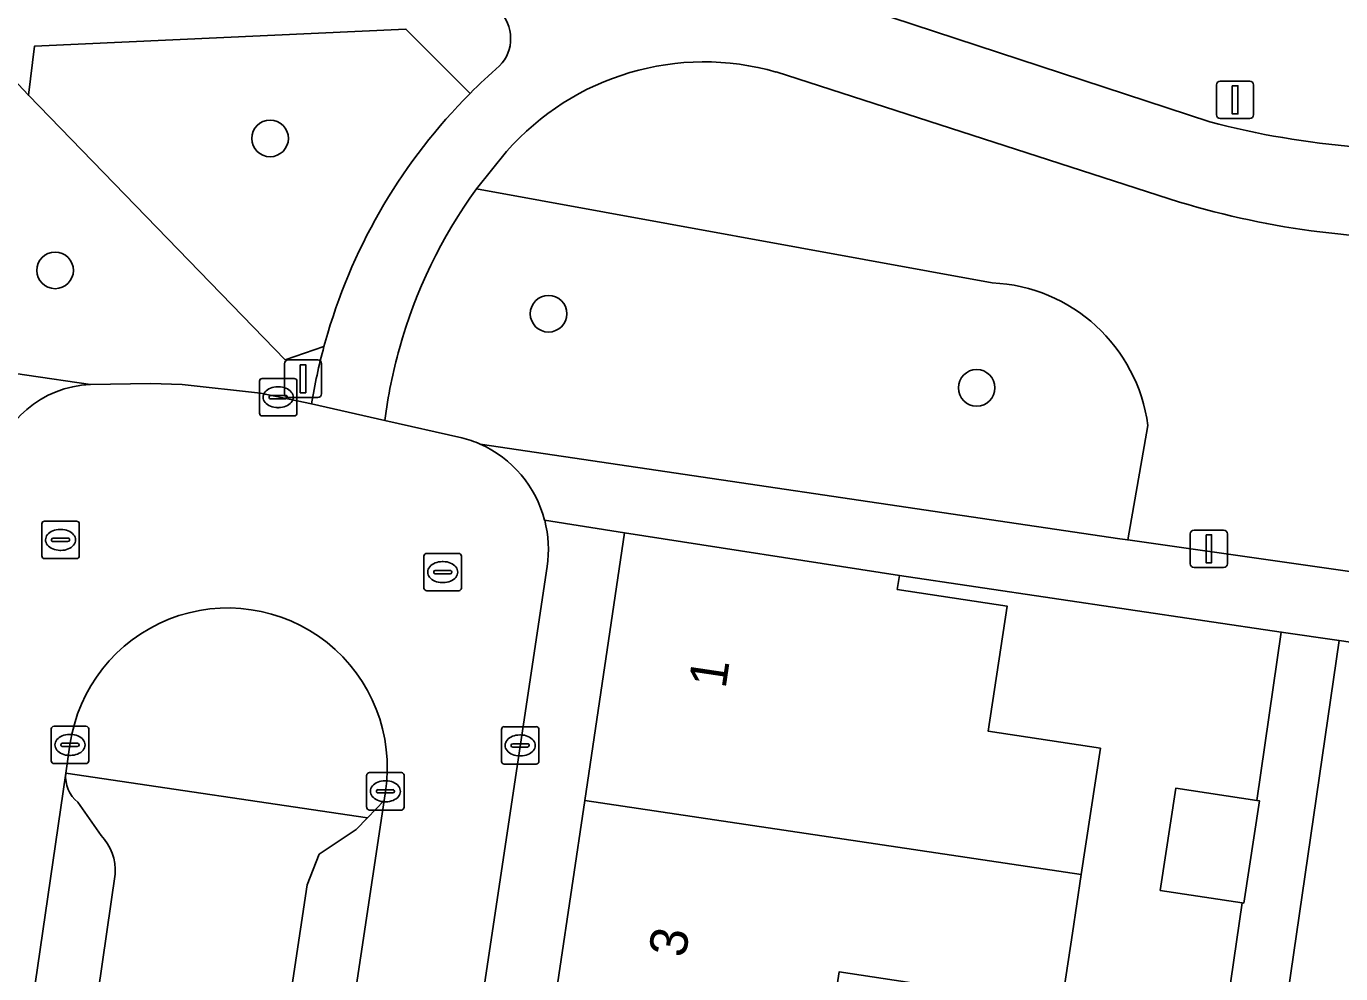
# Model space of a CAD drawing. Extents: x 163683 to 164494, y 382709 to 383872.
# Drawn here: x 164102.44 to 164137.55, y 383063.32 to 383088.61 of the extents above; entities that cross this region are included whole.
import ezdxf

# ---------------------------------------------------------------- set-up
doc = ezdxf.new("R2010")
doc.units = 0
for name, color, linetype in [('IMGEO_Boom', 7, 'Continuous'), ('IMGEO_Erf', 7, 'Continuous'), ('IMGEO_Groenvoorziening', 7, 'Continuous'), ('IMGEO_Kolk', 7, 'Continuous'), ('IMGEO_Lichtmast', 7, 'Continuous'), ('IMGEO_Pand', 7, 'Continuous'), ('IMGEO_Pand_nummerreeks', 7, 'Continuous'), ('IMGEO_Parkeervlak_open', 7, 'Continuous'), ('IMGEO_Rijbaan_lokaal_open', 7, 'Continuous'), ('IMGEO_Rioolput', 7, 'Continuous'), ('IMGEO_Voetpad_halfverhard', 7, 'Continuous'), ('IMGEO_Voetpad_onverhard', 7, 'Continuous'), ('IMGEO_Voetpad_open', 7, 'Continuous')]:
    doc.layers.add(name, color=color, linetype=linetype)

msp = doc.modelspace()

# ---------------------------------------------------------------- linework, layer by layer
at = {"layer": 'IMGEO_Boom'}
for centre in [(164108.954, 383085.621), (164103.212, 383082.097), (164116.392, 383080.939), (164127.828, 383078.96)]:
    msp.add_circle(centre, 0.489, dxfattribs=at)
at = {"layer": 'IMGEO_Erf'}
for points in [[(164134.915, 383065.209), (164132.733, 383065.541), (164133.149, 383068.274), (164135.312, 383067.944), (164135.965, 383072.44), (164125.764, 383073.946), (164125.708, 383073.578), (164128.64, 383073.132), (164128.133, 383069.794), (164131.135, 383069.339), (164130.623, 383065.966), (164130.384, 383064.396), (164130.091, 383062.468), (164124.158, 383063.368), (164123.625, 383059.857), (164123.087, 383056.319), (164129.021, 383055.419), (164128.733, 383053.521), (164128.499, 383051.98), (164127.982, 383048.577), (164122.049, 383049.477), (164121.476, 383045.707), (164131.862, 383044.198)], [(164146.251, 383060.095), (164140.317, 383060.973), (164140.602, 383062.903), (164140.829, 383064.44), (164141.333, 383067.849), (164147.268, 383066.971), (164147.817, 383070.691), (164137.509, 383072.212), (164133.407, 383043.974), (164143.649, 383042.486), (164144.194, 383046.176), (164138.26, 383047.054), (164138.767, 383050.485), (164136.597, 383050.805), (164136.989, 383053.462), (164139.16, 383053.142), (164139.279, 383053.95), (164145.213, 383053.072), (164145.733, 383056.587)]]:
    msp.add_lwpolyline(points, close=True, dxfattribs=at)
at = {"layer": 'IMGEO_Groenvoorziening'}
for points in [[(164063.914, 383096.136), (164060.271, 383092.698), (164059.314, 383087.6), (164060.473, 383085.465), (164077.551, 383082.956), (164078.62, 383087.621), (164097.665, 383084.707), (164099.049, 383079.797), (164104.156, 383079.047), (164105.76, 383079.073), (164106.604, 383079.047), (164108.694, 383078.814), (164110.063, 383078.532)], [(164110.394, 383080.065), (164109.361, 383079.71), (164102.501, 383086.771), (164098.441, 383091.102)], [(164122.556, 383089.943), (164123.88, 383089.409), (164134.057, 383086.059)], [(164114.296, 383086.819), (164112.582, 383088.541), (164102.66, 383088.082), (164102.501, 383086.771), (164109.361, 383079.71), (164110.394, 383080.065), (164110.494, 383080.419)], [(164133.248, 383083.922), (164122.474, 383087.394)], [(164115.27, 383085.27), (164114.466, 383084.27), (164128.244, 383081.764)], [(164128.244, 383081.764), (164114.466, 383084.27)], [(164112.022, 383078.091), (164114.08, 383077.628)], [(164114.568, 383077.457), (164131.649, 383074.93), (164131.864, 383074.9), (164132.4, 383077.957)], [(164132.4, 383077.957), (164131.864, 383074.9), (164157.283, 383071.277), (164153.793, 383047.768), (164153.917, 383047.788)], [(164103.609, 383069.43), (164103.498, 383068.668), (164111.555, 383067.478), (164111.998, 383067.938), (164112.035, 383068.184)], [(164104.819, 383065.979), (164102.872, 383052.545), (164107.85, 383051.778), (164109.948, 383065.689), (164110.267, 383066.508), (164111.254, 383067.165), (164111.555, 383067.478), (164103.498, 383068.668)], [(164103.822, 383067.893), (164104.439, 383067.008)]]:
    msp.add_lwpolyline(points, dxfattribs=at)
for centre, radius, start, end in [((164120.547, 383080.652), 7.012, 74.0446, 138.8102), ((164125.056, 383076.098), 15.19, 135.1027, 163.4713), ((164139.889, 383108.442), 23.13, 255.3969, 275.1179), ((164125.256, 383076.427), 13.339, 143.9868, 164.4007), ((164139.731, 383105.192), 22.236, 253.0504, 272.8188), ((164128.05, 383077.38), 4.388, 7.5513, 87.4677), ((164128.05, 383077.38), 4.388, 7.5513, 87.4677), ((164124.663, 383076.182), 14.788, 164.7763, 170.8556), ((164125.37, 383076.412), 13.453, 164.4696, 172.8303), ((164113.342, 383074.74), 2.981, 65.714, 75.6641), ((164107.825, 383068.824), 4.259, 351.3566, 171.82), ((164104.369, 383068.577), 0.875, 174.0139, 231.3623), ((164103.435, 383066.052), 1.386, 356.9611, 43.5764)]:
    msp.add_arc(centre, radius, start, end, dxfattribs=at)
at = {"layer": 'IMGEO_Kolk'}
for p, q in [((164108.67, 383078.285), (164108.67, 383079.137)), ((164108.745, 383079.211), (164109.597, 383079.211)), ((164109.671, 383079.137), (164109.671, 383078.285)), ((164108.972, 383078.754), (164109.37, 383078.754)), ((164109.158, 383078.991), (164109.183, 383078.991)), ((164108.929, 383078.705), (164108.929, 383078.717)), ((164109.367, 383078.668), (164108.969, 383078.668)), ((164109.181, 383078.431), (164109.156, 383078.431)), ((164109.413, 383078.717), (164109.413, 383078.705)), ((164109.597, 383078.211), (164108.745, 383078.211)), ((164103.109, 383069), (164103.109, 383069.852)), ((164103.184, 383069.926), (164104.036, 383069.926)), ((164103.597, 383069.706), (164103.622, 383069.706)), ((164104.11, 383069.852), (164104.11, 383069)), ((164115.134, 383068.987), (164115.134, 383069.839)), ((164115.209, 383069.913), (164116.061, 383069.913)), ((164115.622, 383069.693), (164115.647, 383069.693)), ((164116.135, 383069.839), (164116.135, 383068.987)), ((164103.368, 383069.42), (164103.368, 383069.432)), ((164103.806, 383069.383), (164103.408, 383069.383)), ((164103.411, 383069.469), (164103.809, 383069.469)), ((164103.852, 383069.432), (164103.852, 383069.42)), ((164115.393, 383069.407), (164115.393, 383069.419)), ((164115.831, 383069.37), (164115.433, 383069.37)), ((164115.436, 383069.456), (164115.834, 383069.456)), ((164115.877, 383069.419), (164115.877, 383069.407)), ((164104.036, 383068.926), (164103.184, 383068.926)), ((164103.62, 383069.146), (164103.595, 383069.146)), ((164116.061, 383068.913), (164115.209, 383068.913)), ((164115.645, 383069.133), (164115.62, 383069.133)), ((164111.534, 383067.762), (164111.534, 383068.614)), ((164111.609, 383068.688), (164112.461, 383068.688)), ((164112.535, 383068.614), (164112.535, 383067.762)), ((164111.793, 383068.182), (164111.793, 383068.194)), ((164111.836, 383068.231), (164112.234, 383068.231)), ((164112.022, 383068.468), (164112.047, 383068.468)), ((164112.277, 383068.194), (164112.277, 383068.182)), ((164112.231, 383068.145), (164111.833, 383068.145)), ((164112.045, 383067.908), (164112.02, 383067.908)), ((164112.461, 383067.688), (164111.609, 383067.688))]:
    msp.add_line(p, q, dxfattribs=at)
for points in [[(164108.67, 383078.285), (164108.67, 383079.137)], [(164108.745, 383079.211), (164109.597, 383079.211)], [(164109.671, 383079.137), (164109.671, 383078.285)], [(164109.597, 383078.211), (164108.745, 383078.211)], [(164103.109, 383069), (164103.109, 383069.852)], [(164103.184, 383069.926), (164104.036, 383069.926)], [(164104.11, 383069.852), (164104.11, 383069)], [(164115.134, 383068.987), (164115.134, 383069.839)], [(164115.209, 383069.913), (164116.061, 383069.913)], [(164116.135, 383069.839), (164116.135, 383068.987)], [(164104.036, 383068.926), (164103.184, 383068.926)], [(164116.061, 383068.913), (164115.209, 383068.913)], [(164111.534, 383067.762), (164111.534, 383068.614)], [(164111.609, 383068.688), (164112.461, 383068.688)], [(164112.535, 383068.614), (164112.535, 383067.762)], [(164112.461, 383067.688), (164111.609, 383067.688)]]:
    msp.add_lwpolyline(points, dxfattribs=at)
for centre, radius, start, end in [((164108.747, 383079.135), 0.0765, 91.552, 178.448), ((164108.747, 383079.135), 0.0765, 91.552, 178.448), ((164109.595, 383079.135), 0.0765, 1.552, 88.448), ((164109.595, 383079.135), 0.0765, 1.552, 88.448), ((164108.969, 383078.714), 0.0403, 85.8775, 175.7526), ((164109.374, 383078.716), 0.0386, 1.7309, 96.639), ((164108.966, 383078.704), 0.0366, 178.938, 274.7102), ((164109.37, 383078.711), 0.043, 264.8664, 352.4533), ((164108.747, 383078.287), 0.0765, 181.552, 268.448), ((164108.747, 383078.287), 0.0765, 181.552, 268.448), ((164109.595, 383078.287), 0.0765, 271.552, 358.448), ((164109.595, 383078.287), 0.0765, 271.552, 358.448), ((164103.186, 383069.85), 0.0765, 91.552, 178.448), ((164103.186, 383069.85), 0.0765, 91.552, 178.448), ((164104.034, 383069.85), 0.0765, 1.552, 88.448), ((164104.034, 383069.85), 0.0765, 1.552, 88.448), ((164115.211, 383069.837), 0.0765, 91.552, 178.448), ((164115.211, 383069.837), 0.0765, 91.552, 178.448), ((164116.059, 383069.837), 0.0765, 1.552, 88.448), ((164116.059, 383069.837), 0.0765, 1.552, 88.448), ((164103.408, 383069.429), 0.0403, 85.8775, 175.7526), ((164103.405, 383069.419), 0.0366, 178.938, 274.7102), ((164103.809, 383069.426), 0.043, 264.8664, 352.4533), ((164103.813, 383069.431), 0.0386, 1.7309, 96.639), ((164115.433, 383069.416), 0.0403, 85.8775, 175.7526), ((164115.43, 383069.406), 0.0366, 178.938, 274.7102), ((164115.834, 383069.413), 0.043, 264.8664, 352.4533), ((164115.838, 383069.418), 0.0386, 1.7309, 96.639), ((164103.186, 383069.002), 0.0765, 181.552, 268.448), ((164103.186, 383069.002), 0.0765, 181.552, 268.448), ((164104.034, 383069.002), 0.0765, 271.552, 358.448), ((164104.034, 383069.002), 0.0765, 271.552, 358.448), ((164115.211, 383068.989), 0.0765, 181.552, 268.448), ((164115.211, 383068.989), 0.0765, 181.552, 268.448), ((164116.059, 383068.989), 0.0765, 271.552, 358.448), ((164116.059, 383068.989), 0.0765, 271.552, 358.448), ((164111.611, 383068.612), 0.0765, 91.552, 178.448), ((164111.611, 383068.612), 0.0765, 91.552, 178.448), ((164112.459, 383068.612), 0.0765, 1.552, 88.448), ((164112.459, 383068.612), 0.0765, 1.552, 88.448), ((164111.833, 383068.191), 0.0403, 85.8775, 175.7526), ((164112.238, 383068.193), 0.0386, 1.7309, 96.639), ((164111.83, 383068.181), 0.0366, 178.938, 274.7102), ((164112.234, 383068.188), 0.043, 264.8664, 352.4533), ((164111.611, 383067.764), 0.0765, 181.552, 268.448), ((164111.611, 383067.764), 0.0765, 181.552, 268.448), ((164112.459, 383067.764), 0.0765, 271.552, 358.448), ((164112.459, 383067.764), 0.0765, 271.552, 358.448)]:
    msp.add_arc(centre, radius, start, end, dxfattribs=at)
for centre, major_axis, ratio, start_param, end_param in [((164109.157, 383078.711), (-0.387, 0.002), 0.722429, 4.712389, 7.853982), ((164109.182, 383078.711), (-0.39, 0.002), 0.717154, 1.570796, 4.712389), ((164103.596, 383069.426), (-0.387, 0.002), 0.722429, 4.712389, 7.853982), ((164103.621, 383069.426), (-0.39, 0.002), 0.717154, 1.570796, 4.712389), ((164115.621, 383069.413), (-0.387, 0.002), 0.722429, 4.712389, 7.853982), ((164115.646, 383069.413), (-0.39, 0.002), 0.717154, 1.570796, 4.712389), ((164112.021, 383068.188), (-0.387, 0.002), 0.722429, 4.712389, 7.853982), ((164112.046, 383068.188), (-0.39, 0.002), 0.717154, 1.570796, 4.712389)]:
    msp.add_ellipse(centre, major_axis=major_axis, ratio=ratio, start_param=start_param, end_param=end_param, dxfattribs=at)
at = {"layer": 'IMGEO_Lichtmast'}
for p, q in [((164134.335, 383087.15), (164135.125, 383087.15)), ((164135.125, 383087.15), (164134.335, 383087.15)), ((164134.235, 383086.25), (164134.235, 383087.05)), ((164134.235, 383087.05), (164134.235, 383086.25)), ((164135.225, 383087.05), (164135.225, 383086.25)), ((164135.225, 383086.25), (164135.225, 383087.05)), ((164135.125, 383086.15), (164134.335, 383086.15)), ((164134.335, 383086.15), (164135.125, 383086.15)), ((164109.338, 383078.804), (164109.338, 383079.604)), ((164109.338, 383079.604), (164109.338, 383078.804)), ((164109.438, 383079.704), (164110.228, 383079.704)), ((164110.228, 383079.704), (164109.438, 383079.704)), ((164110.328, 383079.604), (164110.328, 383078.804)), ((164110.328, 383078.804), (164110.328, 383079.604)), ((164110.228, 383078.704), (164109.438, 383078.704)), ((164109.438, 383078.704), (164110.228, 383078.704)), ((164133.534, 383074.263), (164133.534, 383075.063)), ((164133.534, 383075.063), (164133.534, 383074.263)), ((164133.634, 383075.163), (164134.424, 383075.163)), ((164134.424, 383075.163), (164133.634, 383075.163)), ((164134.524, 383075.063), (164134.524, 383074.263)), ((164134.524, 383074.263), (164134.524, 383075.063)), ((164134.424, 383074.163), (164133.634, 383074.163)), ((164133.634, 383074.163), (164134.424, 383074.163))]:
    msp.add_line(p, q, dxfattribs=at)
for points in [[(164134.655, 383087.025), (164134.805, 383087.025), (164134.805, 383086.275), (164134.655, 383086.275), (164134.655, 383087.025)], [(164109.758, 383079.579), (164109.908, 383079.579), (164109.908, 383078.829), (164109.758, 383078.829), (164109.758, 383079.579)], [(164133.954, 383075.038), (164134.104, 383075.038), (164134.104, 383074.288), (164133.954, 383074.288), (164133.954, 383075.038)]]:
    msp.add_lwpolyline(points, dxfattribs=at)
for centre, start, end in [((164134.335, 383087.05), 90, 180), ((164134.335, 383087.05), 90, 180), ((164135.125, 383087.05), 0, 90), ((164135.125, 383087.05), 360, 90), ((164134.335, 383086.25), 180, 270), ((164134.335, 383086.25), 180, 270), ((164135.125, 383086.25), 270, 0), ((164135.125, 383086.25), 270, 0), ((164109.438, 383079.604), 90, 180), ((164109.438, 383079.604), 90, 180), ((164110.228, 383079.604), 0, 90), ((164110.228, 383079.604), 360, 90), ((164109.438, 383078.804), 180, 270), ((164109.438, 383078.804), 180, 270), ((164110.228, 383078.804), 270, 0), ((164110.228, 383078.804), 270, 0), ((164133.634, 383075.063), 90, 180), ((164133.634, 383075.063), 90, 180), ((164134.424, 383075.063), 0, 90), ((164134.424, 383075.063), 360, 90), ((164133.634, 383074.263), 180, 270), ((164133.634, 383074.263), 180, 270), ((164134.424, 383074.263), 270, 0), ((164134.424, 383074.263), 270, 0)]:
    msp.add_arc(centre, 0.1, start, end, dxfattribs=at)
at = {"layer": 'IMGEO_Pand'}
for points in [[(164125.764, 383073.946), (164118.425, 383075.085), (164117.361, 383067.94), (164130.623, 383065.966), (164131.135, 383069.339), (164128.133, 383069.794), (164128.64, 383073.132), (164125.708, 383073.578)], [(164135.379, 383067.934), (164135.312, 383067.944), (164133.149, 383068.274), (164132.733, 383065.541), (164134.915, 383065.209), (164134.963, 383065.202)], [(164117.361, 383067.94), (164116.32, 383060.944), (164123.625, 383059.857), (164124.158, 383063.368), (164130.091, 383062.468), (164130.384, 383064.396), (164130.623, 383065.966)]]:
    msp.add_lwpolyline(points, close=True, dxfattribs=at)
at = {"layer": 'IMGEO_Parkeervlak_open'}
for points in [[(164103.498, 383068.668), (164100.553, 383048.49), (164100.461, 383047.857), (164101.249, 383048.786), (164101.998, 383049.306), (164102.507, 383050.03), (164102.872, 383052.545), (164104.819, 383065.979)], [(164104.439, 383067.008), (164103.822, 383067.893)], [(164108.792, 383046.581), (164108.886, 383047.207), (164111.998, 383067.938), (164111.555, 383067.478), (164111.254, 383067.165), (164110.267, 383066.508), (164109.948, 383065.689), (164107.85, 383051.778), (164107.509, 383049.517)]]:
    msp.add_lwpolyline(points, dxfattribs=at)
for centre, radius, start, end in [((164104.369, 383068.577), 0.875, 174.0139, 231.3623), ((164103.435, 383066.052), 1.386, 356.9611, 43.5764)]:
    msp.add_arc(centre, radius, start, end, dxfattribs=at)
at = {"layer": 'IMGEO_Rijbaan_lokaal_open'}
for points in [[(164114.08, 383077.628), (164112.022, 383078.091), (164110.063, 383078.532), (164108.694, 383078.814), (164106.604, 383079.047), (164105.76, 383079.073), (164104.156, 383079.047)], [(164101.537, 383076.808), (164100.461, 383070.545), (164097.263, 383048.949), (164100.553, 383048.49), (164103.498, 383068.668), (164103.609, 383069.43)], [(164112.035, 383068.184), (164111.998, 383067.938), (164108.886, 383047.207), (164112.228, 383046.662), (164116.353, 383074.19)]]:
    msp.add_lwpolyline(points, dxfattribs=at)
for centre, radius, start, end in [((164104.247, 383076.289), 2.759, 91.8913, 169.1634), ((164113.342, 383074.74), 2.981, 65.714, 75.6641), ((164113.312, 383074.651), 3.074, 14.5441, 65.8933), ((164113.312, 383074.648), 3.076, 351.4381, 14.5972), ((164107.825, 383068.824), 4.259, 351.3566, 171.82)]:
    msp.add_arc(centre, radius, start, end, dxfattribs=at)
at = {"layer": 'IMGEO_Rioolput'}
for p, q in [((164102.857, 383074.475), (164102.857, 383075.327)), ((164102.932, 383075.401), (164103.784, 383075.401)), ((164103.858, 383075.327), (164103.858, 383074.475)), ((164103.116, 383074.895), (164103.116, 383074.907)), ((164103.159, 383074.944), (164103.557, 383074.944)), ((164103.345, 383075.181), (164103.37, 383075.181)), ((164103.6, 383074.907), (164103.6, 383074.895)), ((164103.554, 383074.858), (164103.156, 383074.858)), ((164103.368, 383074.621), (164103.343, 383074.621)), ((164113.14, 383074.541), (164113.992, 383074.541)), ((164103.784, 383074.401), (164102.932, 383074.401)), ((164113.065, 383073.615), (164113.065, 383074.467)), ((164113.553, 383074.321), (164113.578, 383074.321)), ((164114.066, 383074.467), (164114.066, 383073.615)), ((164113.324, 383074.035), (164113.324, 383074.047)), ((164113.762, 383073.998), (164113.364, 383073.998)), ((164113.367, 383074.084), (164113.765, 383074.084)), ((164113.808, 383074.047), (164113.808, 383074.035)), ((164113.992, 383073.541), (164113.14, 383073.541)), ((164113.576, 383073.761), (164113.551, 383073.761))]:
    msp.add_line(p, q, dxfattribs=at)
for points in [[(164102.857, 383074.475), (164102.857, 383075.327)], [(164102.932, 383075.401), (164103.784, 383075.401)], [(164103.858, 383075.327), (164103.858, 383074.475)], [(164113.14, 383074.541), (164113.992, 383074.541)], [(164103.784, 383074.401), (164102.932, 383074.401)], [(164113.065, 383073.615), (164113.065, 383074.467)], [(164114.066, 383074.467), (164114.066, 383073.615)], [(164113.992, 383073.541), (164113.14, 383073.541)]]:
    msp.add_lwpolyline(points, dxfattribs=at)
for centre, radius, start, end in [((164102.934, 383075.325), 0.0765, 91.552, 178.448), ((164102.934, 383075.325), 0.0765, 91.552, 178.448), ((164103.782, 383075.325), 0.0765, 1.552, 88.448), ((164103.782, 383075.325), 0.0765, 1.552, 88.448), ((164103.156, 383074.904), 0.0403, 85.8775, 175.7526), ((164103.153, 383074.894), 0.0366, 178.938, 274.7102), ((164103.557, 383074.901), 0.043, 264.8664, 352.4533), ((164103.561, 383074.906), 0.0386, 1.7309, 96.639), ((164113.142, 383074.465), 0.0765, 91.552, 178.448), ((164113.142, 383074.465), 0.0765, 91.552, 178.448), ((164113.99, 383074.465), 0.0765, 1.552, 88.448), ((164113.99, 383074.465), 0.0765, 1.552, 88.448), ((164102.934, 383074.477), 0.0765, 181.552, 268.448), ((164102.934, 383074.477), 0.0765, 181.552, 268.448), ((164103.782, 383074.477), 0.0765, 271.552, 358.448), ((164103.782, 383074.477), 0.0765, 271.552, 358.448), ((164113.364, 383074.044), 0.0403, 85.8775, 175.7526), ((164113.361, 383074.034), 0.0366, 178.938, 274.7102), ((164113.765, 383074.041), 0.043, 264.8664, 352.4533), ((164113.769, 383074.046), 0.0386, 1.7309, 96.639), ((164113.142, 383073.617), 0.0765, 181.552, 268.448), ((164113.142, 383073.617), 0.0765, 181.552, 268.448), ((164113.99, 383073.617), 0.0765, 271.552, 358.448), ((164113.99, 383073.617), 0.0765, 271.552, 358.448)]:
    msp.add_arc(centre, radius, start, end, dxfattribs=at)
for centre, major_axis, ratio, start_param, end_param in [((164103.344, 383074.901), (-0.387, 0.002), 0.722429, 4.712389, 7.853982), ((164103.369, 383074.901), (-0.39, 0.002), 0.717154, 1.570796, 4.712389), ((164113.552, 383074.041), (-0.387, 0.002), 0.722429, 4.712389, 7.853982), ((164113.577, 383074.041), (-0.39, 0.002), 0.717154, 1.570796, 4.712389)]:
    msp.add_ellipse(centre, major_axis=major_axis, ratio=ratio, start_param=start_param, end_param=end_param, dxfattribs=at)
at = {"layer": 'IMGEO_Voetpad_halfverhard'}
for points in [[(164134.057, 383086.059), (164123.88, 383089.409), (164122.556, 383089.943)], [(164122.474, 383087.394), (164133.248, 383083.922)], [(164114.466, 383084.27), (164115.27, 383085.27)], [(164110.494, 383080.419), (164110.394, 383080.065)], [(164110.063, 383078.532), (164112.022, 383078.091)]]:
    msp.add_lwpolyline(points, dxfattribs=at)
for centre, radius, start, end in [((164114.335, 383088.284), 1.045, 315.9427, 45.9941), ((164124.768, 383076.401), 14.771, 130.9537, 135.1481), ((164120.547, 383080.652), 7.012, 74.0446, 138.8102), ((164125.056, 383076.098), 15.19, 135.1027, 163.4713), ((164139.889, 383108.442), 23.13, 255.3969, 275.1179), ((164125.256, 383076.427), 13.339, 143.9868, 164.4007), ((164139.731, 383105.192), 22.236, 253.0504, 272.8188), ((164124.663, 383076.182), 14.788, 164.7763, 170.8556), ((164125.37, 383076.412), 13.453, 164.4696, 172.8303)]:
    msp.add_arc(centre, radius, start, end, dxfattribs=at)
at = {"layer": 'IMGEO_Voetpad_onverhard'}
msp.add_lwpolyline([(164115.061, 383089.036), (164109.849, 383090.701), (164109.49, 383089.255), (164103.869, 383089.316), (164098.441, 383091.102), (164102.501, 383086.771), (164102.66, 383088.082), (164112.582, 383088.541), (164114.296, 383086.819)], dxfattribs=at)
for centre, radius, start, end in [((164114.335, 383088.284), 1.045, 315.9427, 45.9941), ((164124.768, 383076.401), 14.771, 130.9537, 135.1481)]:
    msp.add_arc(centre, radius, start, end, dxfattribs=at)
at = {"layer": 'IMGEO_Voetpad_open'}
for points in [[(164104.156, 383079.047), (164099.049, 383079.797), (164077.551, 383082.956)], [(164131.864, 383074.9), (164131.649, 383074.93), (164114.568, 383077.457)], [(164116.288, 383075.423), (164118.425, 383075.085), (164125.764, 383073.946), (164135.965, 383072.44), (164137.509, 383072.212), (164147.817, 383070.691), (164155.134, 383069.618), (164154.072, 383062.486), (164153.034, 383055.509), (164151.995, 383048.533), (164150.932, 383041.393), (164152.624, 383041.139), (164153.2, 383044.955), (164153.629, 383045.816), (164153.917, 383047.788), (164153.793, 383047.768), (164157.283, 383071.277), (164131.864, 383074.9)], [(164117.361, 383067.94), (164118.425, 383075.085), (164116.288, 383075.423)], [(164116.353, 383074.19), (164112.228, 383046.662), (164114.215, 383046.807), (164115.278, 383053.948), (164116.32, 383060.944), (164117.361, 383067.94)]]:
    msp.add_lwpolyline(points, dxfattribs=at)
msp.add_lwpolyline([(164137.509, 383072.212), (164135.965, 383072.44), (164135.312, 383067.944), (164135.379, 383067.934), (164134.963, 383065.202), (164134.915, 383065.209), (164131.862, 383044.198), (164133.407, 383043.974)], close=True, dxfattribs=at)
for centre, radius, start, end in [((164104.247, 383076.289), 2.759, 91.8913, 169.1634), ((164113.312, 383074.651), 3.074, 14.5441, 65.8933), ((164113.312, 383074.648), 3.076, 351.4381, 14.5972)]:
    msp.add_arc(centre, radius, start, end, dxfattribs=at)

# ---------------------------------------------------------------- texts
at = {"layer": 'IMGEO_Pand_nummerreeks'}
for s, rotation, p in [('1', 81.5319, (164121.119, 383070.908)), ('3', 81.5321, (164120.05, 383063.725))]:
    msp.add_text(s, height=1, rotation=rotation, dxfattribs=at).set_placement(p)

doc.saveas('drawing.dxf')
